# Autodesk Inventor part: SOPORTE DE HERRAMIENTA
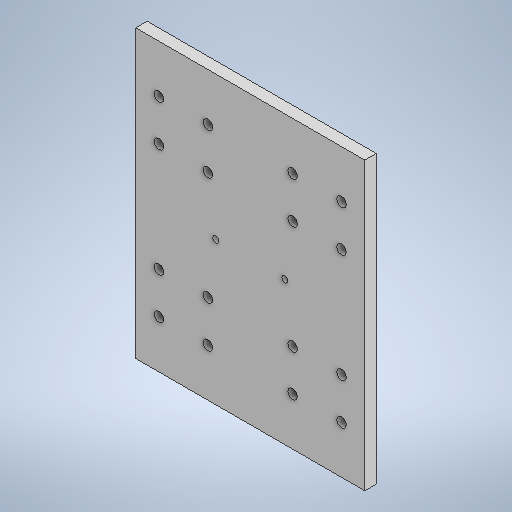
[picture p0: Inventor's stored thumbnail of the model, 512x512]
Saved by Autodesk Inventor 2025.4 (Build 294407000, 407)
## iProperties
Created: 2026-04
Part Number: SOPORTE DE HERRAMIENTA
Material: Steel, Galvanized
Document SubType Name: Modeling
Designer: PC
Density: 7.85 g/cm^3
Appearance: Galvanized
Author: PC
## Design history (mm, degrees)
sketch "Sketch1"
  geometry: L1 (60, -75)-(-60, -75); L2 (-60, -75)-(-60, 75); L3 (-60, 75)-(60, 75); L4 (60, 75)-(60, -75); L5 (60, -75)-(-60, 75); L6 (-60, -75)-(60, 75); 1 further point
  constraints: 12 end point, 2 midpoint, 2 parallel, 1 horizontal, 1 perpendicular
  dimensions: "d0" = 120 distance of L2.end L3.end; "d1" = 150 distance of L1.end L2.end
extrude "Extrusion1" new body sketch "Sketch1" distance "d2" = 6; taper "d3" = 0 deg
sketch "Sketch2"
  geometry: L1 (-47.8, 50)-(-22.2, 50); L2 (-22.2, 50)-(-35, 50); L3 (-35, 82.801)-(-35, 50); L4 (22.2, 50)-(47.8, 50); L5 (47.8, 50)-(35, 50); L6 (35, 82.801)-(35, 50); L7 (-60, 75)-(-60, -75) reference; L8 (60, 75)-(-60, 75) reference; L9 (-60, -75)-(60, -75) reference; C1 r 2.5 at (-47.8, 50); C2 r 2.5 at (-22.2, 50); C3 r 2.5 at (-47.8, 28.4); C4 r 2.5 at (-22.2, 28.4); C5 r 2.5 at (22.2, 50); C6 r 2.5 at (47.8, 50); C7 r 2.5 at (22.2, 28.4); C8 r 2.5 at (47.8, 28.4); C9 r 2.5 at (-47.8, -28.4); C10 r 2.5 at (-22.2, -28.4); C11 r 2.5 at (-47.8, -50); C12 r 2.5 at (-22.2, -50); C13 r 2.5 at (22.2, -28.4); C14 r 2.5 at (47.8, -28.4); C15 r 2.5 at (22.2, -50); C16 r 2.5 at (47.8, -50); 1 further point
  constraints: 16 centre point, 12 end point, 10 horizontal alignment, 10 vertical alignment, 3 perpendicular, 2 midpoint, 1 horizontal
  dimensions: "d4" = 5 diameter of C1; "d5" = 5 diameter of C2; "d6" = 5 diameter of C3; "d7" = 5 diameter of C4; "d8" = 25.6 distance of L1.end L1.start; "d9" = 21.6 distance of C3.centre L1.start; "d10" = 5 diameter of C5; "d11" = 5 diameter of C6; "d12" = 5 diameter of C7; "d13" = 5 diameter of C8; "d14" = 25.6 distance of L4.end L4.start; "d15" = 21.6 distance of C7.centre L4.start; "d16" = 5 diameter of C9; "d17" = 5 diameter of C10; "d18" = 5 diameter of C11; "d19" = 5 diameter of C12; "d20" = 25.6 distance of C10.centre C9.centre; "d21" = 21.6 distance of C11.centre C9.centre; "d22" = 5 diameter of C13; "d23" = 5 diameter of C14; "d24" = 5 diameter of C15; "d25" = 5 diameter of C16; "d26" = 25.6 distance of C14.centre C13.centre; "d27" = 21.6 distance of C15.centre C13.centre; "d28" = 70 distance between parallel lines of L6 L3; "d30" = 25 distance from line of L7 L2.end; "d31" = 25 distance from line of L8 L1.start; "d32" = 25 distance from line of L9 C11.centre
extrude "Extrusion2" cut sketch "Sketch2" extent not by distance; stored distance "d33" = 0; taper "d34" = 0 deg
sketch "Sketch3"
  geometry: L1 (-16.5, 4.198)-(-16.5, -4.693); L2 (16.5, 5.087)-(16.5, -4.199); C1 r 1.6 at (-18.1, 0); C2 r 1.6 at (18.1, 0); 1 further point
  constraints: 4 end point, 2 centre point, 2 tangent, 2 vertical
  dimensions: "d35" = 3.2 diameter of C1; "d36" = 3.2 diameter of C2; "d37" = 33 distance between parallel lines of L2 L1; "d38" = 16.5 distance from line of point (0, 0) L1
extrude "Extrusion3" cut sketch "Sketch3" distance "d39" = 10; taper "d40" = 0 deg
body "Solid1"
